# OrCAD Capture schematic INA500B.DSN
size A
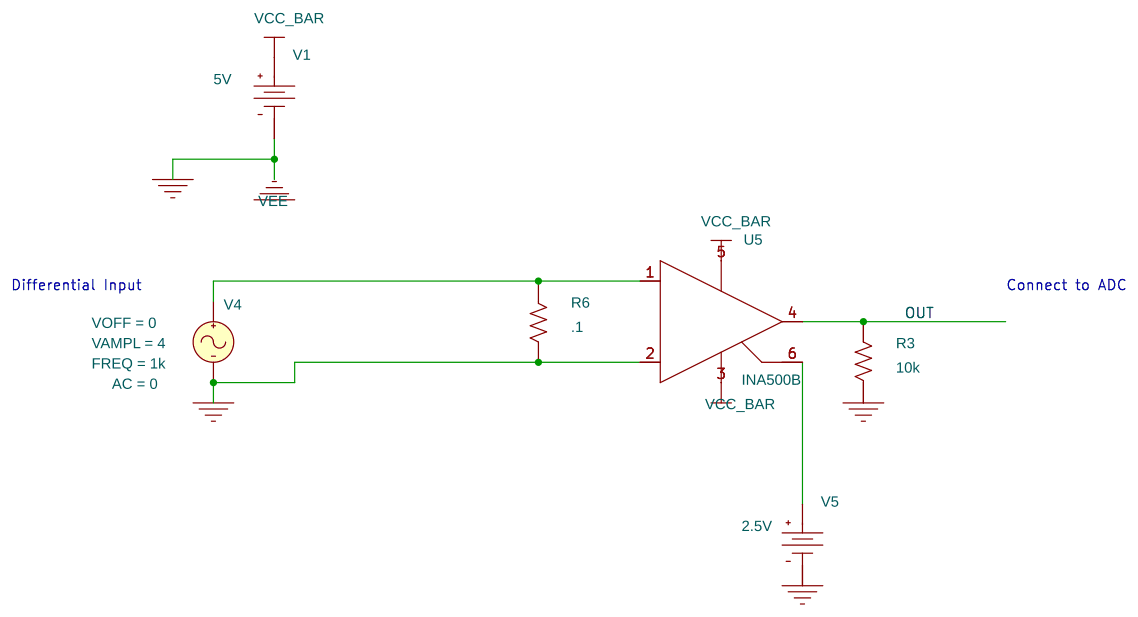
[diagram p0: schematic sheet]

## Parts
R3  10k  [AXRC05]
R6  .1  [AXRC05]
U5  INA500B
V1  VDC
V4  VSIN
V5  VDC

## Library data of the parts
R3 R6 = R
U5 = INA500B
V1 = VDC: DC: 5V
V4 = VSIN: AC: 0; FREQ: 1k; VAMPL: 4; VOFF: 0
V5 = VDC: DC: 2.5V

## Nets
Vcc: U5.5(V+) V1.0(+)
0: R3.1 R6.2 U5.2(-) U5.3(V-) V1.1(-) V4.2(-) V5.1(-)
OUT: R3.2 U5.4(OUT)
N04489: R6.1 U5.1(+) V4.1(+)
N04625: U5.6(REF) V5.0(+)

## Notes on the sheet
- Differential Input
- Connect to ADC
